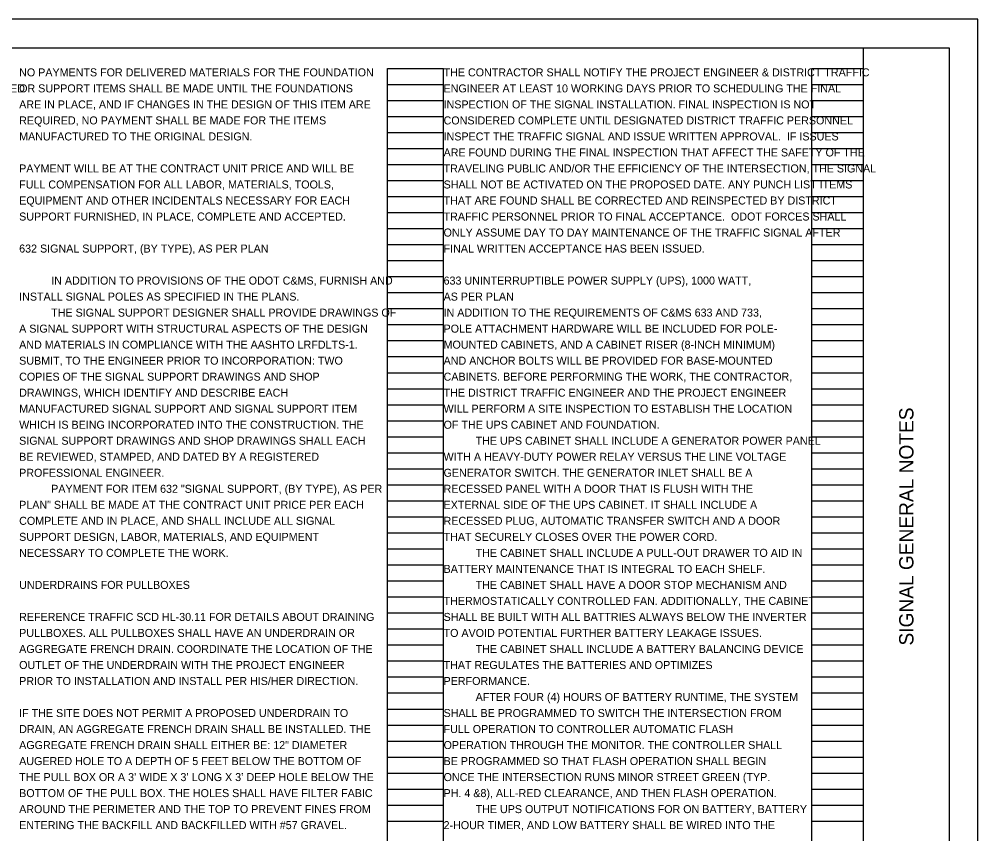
# Model space of a CAD drawing. Extents: x 0 to 54.7, y -11 to 22.
# Drawn here: x 17.24 to 34, y 7.76 to 22 of the extents above; entities that cross this region are included whole.
import ezdxf

# ---------------------------------------------------------------- set-up
doc = ezdxf.new("R2010")
doc.units = 0
for name, color, linetype in [('SH_Border', 7, 'Continuous'), ('SH_Cut_Line', 7, 'Continuous'), ('SH_Data', 7, 'Continuous'), ('SH_Text', 7, 'Continuous')]:
    doc.layers.add(name, color=color, linetype=linetype)

msp = doc.modelspace()

# ---------------------------------------------------------------- linework, layer by layer
at = {"layer": 'SH_Border'}
msp.add_line((32, 0.5), (32, 21.5), dxfattribs=at)
msp.add_lwpolyline([(1.5, 21.5), (33.5, 21.5), (33.5, 0.5), (1.5, 0.5)], close=True, dxfattribs=at)
at = {"layer": 'SH_Cut_Line'}
msp.add_lwpolyline([(0, 0), (34, 0), (34, 22), (0, 22)], close=True, dxfattribs=at)
at = {"layer": 'SH_Data'}
for p, q in [((23.68, 0.98), (23.68, 21.14)), ((23.68, 21.14), (24.66, 21.14)), ((24.66, 0.98), (24.66, 21.14)), ((31.1, 0.98), (31.1, 21.14)), ((31.1, 21.14), (32, 21.14)), ((32, 0.98), (32, 21.14)), ((23.68, 20.86), (24.66, 20.86)), ((31.1, 20.86), (32, 20.86)), ((23.68, 20.58), (24.66, 20.58)), ((31.1, 20.58), (32, 20.58)), ((23.68, 20.3), (24.66, 20.3)), ((31.1, 20.3), (32, 20.3)), ((23.68, 20.02), (24.66, 20.02)), ((31.1, 20.02), (32, 20.02)), ((23.68, 19.74), (24.66, 19.74)), ((31.1, 19.74), (32, 19.74)), ((23.68, 19.46), (24.66, 19.46)), ((31.1, 19.46), (32, 19.46)), ((23.68, 19.18), (24.66, 19.18)), ((31.1, 19.18), (32, 19.18)), ((23.68, 18.9), (24.66, 18.9)), ((31.1, 18.9), (32, 18.9)), ((23.68, 18.62), (24.66, 18.62)), ((31.1, 18.62), (32, 18.62)), ((23.68, 18.34), (24.66, 18.34)), ((31.1, 18.34), (32, 18.34)), ((23.68, 18.06), (24.66, 18.06)), ((31.1, 18.06), (32, 18.06)), ((23.68, 17.78), (24.66, 17.78)), ((31.1, 17.78), (32, 17.78)), ((23.68, 17.5), (24.66, 17.5)), ((31.1, 17.5), (32, 17.5)), ((23.68, 17.22), (24.66, 17.22)), ((31.1, 17.22), (32, 17.22)), ((23.68, 16.94), (24.66, 16.94)), ((31.1, 16.94), (32, 16.94)), ((23.68, 16.66), (24.66, 16.66)), ((31.1, 16.66), (32, 16.66)), ((23.68, 16.38), (24.66, 16.38)), ((31.1, 16.38), (32, 16.38)), ((23.68, 16.1), (24.66, 16.1)), ((31.1, 16.1), (32, 16.1)), ((23.68, 15.82), (24.66, 15.82)), ((31.1, 15.82), (32, 15.82)), ((23.68, 15.54), (24.66, 15.54)), ((31.1, 15.54), (32, 15.54)), ((23.68, 15.26), (24.66, 15.26)), ((31.1, 15.26), (32, 15.26)), ((23.68, 14.98), (24.66, 14.98)), ((31.1, 14.98), (32, 14.98)), ((23.68, 14.7), (24.66, 14.7)), ((31.1, 14.7), (32, 14.7)), ((23.68, 14.42), (24.66, 14.42)), ((31.1, 14.42), (32, 14.42)), ((23.68, 14.14), (24.66, 14.14)), ((31.1, 14.14), (32, 14.14)), ((23.68, 13.86), (24.66, 13.86)), ((31.1, 13.86), (32, 13.86)), ((23.68, 13.58), (24.66, 13.58)), ((31.1, 13.58), (32, 13.58)), ((23.68, 13.3), (24.66, 13.3)), ((31.1, 13.3), (32, 13.3)), ((23.68, 13.02), (24.66, 13.02)), ((31.1, 13.02), (32, 13.02)), ((23.68, 12.74), (24.66, 12.74)), ((31.1, 12.74), (32, 12.74)), ((23.68, 12.46), (24.66, 12.46)), ((31.1, 12.46), (32, 12.46)), ((23.68, 12.18), (24.66, 12.18)), ((31.1, 12.18), (32, 12.18)), ((23.68, 11.9), (24.66, 11.9)), ((31.1, 11.9), (32, 11.9)), ((23.68, 11.62), (24.66, 11.62)), ((31.1, 11.62), (32, 11.62)), ((23.68, 11.34), (24.66, 11.34)), ((31.1, 11.34), (32, 11.34)), ((23.68, 11.06), (24.66, 11.06)), ((31.1, 11.06), (32, 11.06)), ((23.68, 10.78), (24.66, 10.78)), ((31.1, 10.78), (32, 10.78)), ((23.68, 10.5), (24.66, 10.5)), ((31.1, 10.5), (32, 10.5)), ((23.68, 10.22), (24.66, 10.22)), ((31.1, 10.22), (32, 10.22)), ((23.68, 9.94), (24.66, 9.94)), ((31.1, 9.94), (32, 9.94)), ((23.68, 9.66), (24.66, 9.66)), ((31.1, 9.66), (32, 9.66)), ((23.68, 9.38), (24.66, 9.38)), ((31.1, 9.38), (32, 9.38)), ((23.68, 9.1), (24.66, 9.1)), ((31.1, 9.1), (32, 9.1)), ((23.68, 8.82), (24.66, 8.82)), ((31.1, 8.82), (32, 8.82)), ((23.68, 8.54), (24.66, 8.54)), ((31.1, 8.54), (32, 8.54)), ((23.68, 8.26), (24.66, 8.26)), ((31.1, 8.26), (32, 8.26)), ((23.68, 7.98), (24.66, 7.98)), ((31.1, 7.98), (32, 7.98))]:
    msp.add_line(p, q, dxfattribs=at)

# ---------------------------------------------------------------- texts
msp.add_text('SIGNAL GENERAL NOTES', height=0.25, rotation=90, dxfattribs=at).set_placement((32.875, 11.05))
at = {"layer": 'SH_Text'}
for s, p in [('NO PAYMENTS FOR DELIVERED MATERIALS FOR THE FOUNDATION', (17.24, 21)), ('THE CONTRACTOR SHALL NOTIFY THE PROJECT ENGINEER & DISTRICT TRAFFIC', (24.66, 21)), ('LOCAL AGENCY ARE NOT REMOVED, THE CONTRACTOR SHALL, WHEN DIRECTED', (9.82, 20.72)), ('OR SUPPORT ITEMS SHALL BE MADE UNTIL THE FOUNDATIONS', (17.24, 20.72)), ('ENGINEER AT LEAST 10 WORKING DAYS PRIOR TO SCHEDULING THE FINAL', (24.66, 20.72)), ('ARE IN PLACE, AND IF CHANGES IN THE DESIGN OF THIS ITEM ARE', (17.24, 20.44)), ('INSPECTION OF THE SIGNAL INSTALLATION. FINAL INSPECTION IS NOT', (24.66, 20.44)), ('REQUIRED, NO PAYMENT SHALL BE MADE FOR THE ITEMS', (17.24, 20.16)), ('CONSIDERED COMPLETE UNTIL DESIGNATED DISTRICT TRAFFIC PERSONNEL', (24.66, 20.16)), ('MANUFACTURED TO THE ORIGINAL DESIGN.', (17.24, 19.88)), ('INSPECT THE TRAFFIC SIGNAL AND ISSUE WRITTEN APPROVAL.  IF ISSUES', (24.66, 19.88)), ('ARE FOUND DURING THE FINAL INSPECTION THAT AFFECT THE SAFETY OF THE', (24.66, 19.6)), ('PAYMENT WILL BE AT THE CONTRACT UNIT PRICE AND WILL BE', (17.24, 19.32)), ('TRAVELING PUBLIC AND/OR THE EFFICIENCY OF THE INTERSECTION, THE SIGNAL', (24.66, 19.32)), ('FULL COMPENSATION FOR ALL LABOR, MATERIALS, TOOLS,', (17.24, 19.04)), ('SHALL NOT BE ACTIVATED ON THE PROPOSED DATE. ANY PUNCH LIST ITEMS', (24.66, 19.04)), ('EQUIPMENT AND OTHER INCIDENTALS NECESSARY FOR EACH', (17.24, 18.76)), ('THAT ARE FOUND SHALL BE CORRECTED AND REINSPECTED BY DISTRICT', (24.66, 18.76)), ('SUPPORT FURNISHED, IN PLACE, COMPLETE AND ACCEPTED.', (17.24, 18.48)), ('TRAFFIC PERSONNEL PRIOR TO FINAL ACCEPTANCE.  ODOT FORCES SHALL', (24.66, 18.48)), ('ONLY ASSUME DAY TO DAY MAINTENANCE OF THE TRAFFIC SIGNAL AFTER', (24.66, 18.2)), ('632 SIGNAL SUPPORT, (BY TYPE), AS PER PLAN', (17.24, 17.92)), ('FINAL WRITTEN ACCEPTANCE HAS BEEN ISSUED.', (24.66, 17.92)), ('IN ADDITION TO PROVISIONS OF THE ODOT C&MS, FURNISH AND', (17.8, 17.36)), ('633 UNINTERRUPTIBLE POWER SUPPLY (UPS), 1000 WATT,', (24.66, 17.36)), ('INSTALL SIGNAL POLES AS SPECIFIED IN THE PLANS.', (17.24, 17.08)), ('AS PER PLAN', (24.66, 17.08)), ('THE SIGNAL SUPPORT DESIGNER SHALL PROVIDE DRAWINGS OF', (17.8, 16.8)), ('IN ADDITION TO THE REQUIREMENTS OF C&MS 633 AND 733,', (24.66, 16.8)), ('A SIGNAL SUPPORT WITH STRUCTURAL ASPECTS OF THE DESIGN', (17.24, 16.52)), ('POLE ATTACHMENT HARDWARE WILL BE INCLUDED FOR POLE-', (24.66, 16.52)), ('AND MATERIALS IN COMPLIANCE WITH THE AASHTO LRFDLTS-1.', (17.24, 16.24)), ('MOUNTED CABINETS, AND A CABINET RISER (8-INCH MINIMUM)', (24.66, 16.24)), ('SUBMIT, TO THE ENGINEER PRIOR TO INCORPORATION: TWO', (17.24, 15.96)), ('AND ANCHOR BOLTS WILL BE PROVIDED FOR BASE-MOUNTED', (24.66, 15.96)), ('COPIES OF THE SIGNAL SUPPORT DRAWINGS AND SHOP', (17.24, 15.68)), ('CABINETS. BEFORE PERFORMING THE WORK, THE CONTRACTOR,', (24.66, 15.68)), ('DRAWINGS, WHICH IDENTIFY AND DESCRIBE EACH', (17.24, 15.4)), ('THE DISTRICT TRAFFIC ENGINEER AND THE PROJECT ENGINEER', (24.66, 15.4)), ('MANUFACTURED SIGNAL SUPPORT AND SIGNAL SUPPORT ITEM', (17.24, 15.12)), ('WILL PERFORM A SITE INSPECTION TO ESTABLISH THE LOCATION', (24.66, 15.12)), ('WHICH IS BEING INCORPORATED INTO THE CONSTRUCTION. THE', (17.24, 14.84)), ('OF THE UPS CABINET AND FOUNDATION.', (24.66, 14.84)), ('SIGNAL SUPPORT DRAWINGS AND SHOP DRAWINGS SHALL EACH', (17.24, 14.56)), ('THE UPS CABINET SHALL INCLUDE A GENERATOR POWER PANEL', (25.22, 14.56)), ('BE REVIEWED, STAMPED, AND DATED BY A REGISTERED', (17.24, 14.28)), ('WITH A HEAVY-DUTY POWER RELAY VERSUS THE LINE VOLTAGE', (24.66, 14.28)), ('PROFESSIONAL ENGINEER.', (17.24, 14)), ('GENERATOR SWITCH. THE GENERATOR INLET SHALL BE A', (24.66, 14)), ('PAYMENT FOR ITEM 632 "SIGNAL SUPPORT, (BY TYPE), AS PER', (17.8, 13.72)), ('RECESSED PANEL WITH A DOOR THAT IS FLUSH WITH THE', (24.66, 13.72)), ('PLAN" SHALL BE MADE AT THE CONTRACT UNIT PRICE PER EACH', (17.24, 13.44)), ('EXTERNAL SIDE OF THE UPS CABINET. IT SHALL INCLUDE A', (24.66, 13.44)), ('COMPLETE AND IN PLACE, AND SHALL INCLUDE ALL SIGNAL', (17.24, 13.16)), ('RECESSED PLUG, AUTOMATIC TRANSFER SWITCH AND A DOOR', (24.66, 13.16)), ('SUPPORT DESIGN, LABOR, MATERIALS, AND EQUIPMENT', (17.24, 12.88)), ('THAT SECURELY CLOSES OVER THE POWER CORD.', (24.66, 12.88)), ('NECESSARY TO COMPLETE THE WORK.', (17.24, 12.6)), ('THE CABINET SHALL INCLUDE A PULL-OUT DRAWER TO AID IN', (25.22, 12.6)), ('BATTERY MAINTENANCE THAT IS INTEGRAL TO EACH SHELF.', (24.66, 12.32)), ('UNDERDRAINS FOR PULLBOXES', (17.24, 12.04)), ('THE CABINET SHALL HAVE A DOOR STOP MECHANISM AND', (25.22, 12.04)), ('THERMOSTATICALLY CONTROLLED FAN. ADDITIONALLY, THE CABINET', (24.66, 11.76)), ('REFERENCE TRAFFIC SCD HL-30.11 FOR DETAILS ABOUT DRAINING', (17.24, 11.48)), ('SHALL BE BUILT WITH ALL BATTRIES ALWAYS BELOW THE INVERTER', (24.66, 11.48)), ('PULLBOXES. ALL PULLBOXES SHALL HAVE AN UNDERDRAIN OR', (17.24, 11.2)), ('TO AVOID POTENTIAL FURTHER BATTERY LEAKAGE ISSUES.', (24.66, 11.2)), ('AGGREGATE FRENCH DRAIN. COORDINATE THE LOCATION OF THE', (17.24, 10.92)), ('THE CABINET SHALL INCLUDE A BATTERY BALANCING DEVICE', (25.22, 10.92)), ('OUTLET OF THE UNDERDRAIN WITH THE PROJECT ENGINEER', (17.24, 10.64)), ('THAT REGULATES THE BATTERIES AND OPTIMIZES', (24.66, 10.64)), ('PRIOR TO INSTALLATION AND INSTALL PER HIS/HER DIRECTION.', (17.24, 10.36)), ('PERFORMANCE.', (24.66, 10.36)), ('AFTER FOUR (4) HOURS OF BATTERY RUNTIME, THE SYSTEM', (25.22, 10.08)), ('IF THE SITE DOES NOT PERMIT A PROPOSED UNDERDRAIN TO', (17.24, 9.8)), ('SHALL BE PROGRAMMED TO SWITCH THE INTERSECTION FROM', (24.66, 9.8)), ('DRAIN, AN AGGREGATE FRENCH DRAIN SHALL BE INSTALLED. THE', (17.24, 9.52)), ('FULL OPERATION TO CONTROLLER AUTOMATIC FLASH', (24.66, 9.52)), ('AGGREGATE FRENCH DRAIN SHALL EITHER BE: 12" DIAMETER', (17.24, 9.24)), ('OPERATION THROUGH THE MONITOR. THE CONTROLLER SHALL', (24.66, 9.24)), ('AUGERED HOLE TO A DEPTH OF 5 FEET BELOW THE BOTTOM OF', (17.24, 8.96)), ('BE PROGRAMMED SO THAT FLASH OPERATION SHALL BEGIN', (24.66, 8.96)), ('THE PULL BOX OR A 3’ WIDE X 3’ LONG X 3’ DEEP HOLE BELOW THE', (17.24, 8.68)), ('ONCE THE INTERSECTION RUNS MINOR STREET GREEN (TYP.', (24.66, 8.68)), ('BOTTOM OF THE PULL BOX. THE HOLES SHALL HAVE FILTER FABIC', (17.24, 8.4)), ('PH. 4 &8), ALL-RED CLEARANCE, AND THEN FLASH OPERATION.', (24.66, 8.4)), ('AROUND THE PERIMETER AND THE TOP TO PREVENT FINES FROM', (17.24, 8.12)), ('THE UPS OUTPUT NOTIFICATIONS FOR ON BATTERY, BATTERY', (25.22, 8.12)), ('ENTERING THE BACKFILL AND BACKFILLED WITH #57 GRAVEL.', (17.24, 7.84)), ('2-HOUR TIMER, AND LOW BATTERY SHALL BE WIRED INTO THE', (24.66, 7.84))]:
    msp.add_text(s, height=0.14, dxfattribs=at).set_placement(p)

doc.saveas('drawing.dxf')
